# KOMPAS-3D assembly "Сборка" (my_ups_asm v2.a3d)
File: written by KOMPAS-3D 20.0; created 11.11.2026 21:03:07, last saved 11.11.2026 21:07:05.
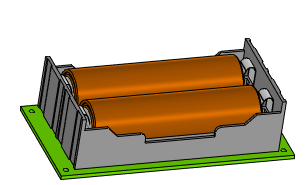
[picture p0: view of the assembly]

Document properties: Полное имя файла: D:\myProjects\Progect_esp32\box_compas\ups 18650\my_ups_asm v2.a3d

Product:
- Part/product: Сборка
    Масса: 0.425781
  - Component [detail]: Деталь  | qty 2  | Масса: 0.12809; source file: 18650 acc.m3d
  - Component [detail]: Деталь  | Масса: 0.123603; source file: battery 18650 case x2.m3d
  - Component [detail]: Деталь  | Масса: 0.0459981; source file: my_ups v2.m3d

Referenced files in D:\myProjects\Progect_esp32\box_compas\ups 18650\: my_ups v2.m3d, battery 18650 case x2.m3d, 18650 acc.m3d
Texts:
  Деталь (1)
  Деталь (2)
